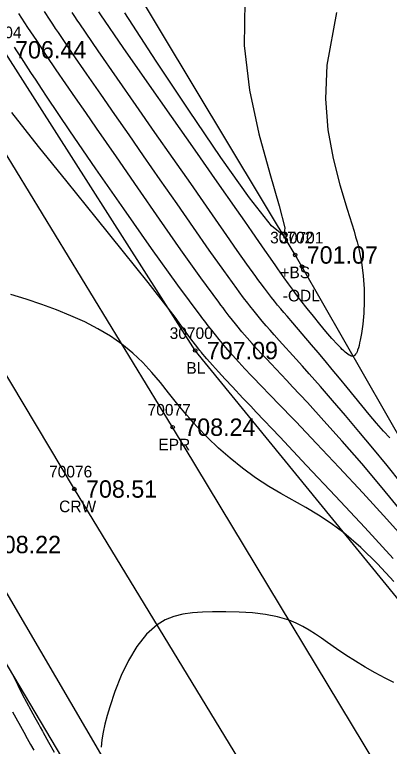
# Model space of a CAD drawing. Extents: x 1376587 to 1378239, y 1000335 to 1003031.
# Drawn here: x 1377497.4 to 1377529.7, y 1001412.8 to 1001475.9 of the extents above; entities that cross this region are included whole.
import ezdxf

# ---------------------------------------------------------------- set-up
doc = ezdxf.new("R2010")
doc.units = 0
for name, color, linetype in [('RD_DTM_BkLn1', 7, 'Continuous'), ('RD_DTM_BkLn2', 7, 'Continuous'), ('RD_DTM_BkLn_txCode', 7, 'Continuous'), ('RD_DTM_Major1', 7, 'Continuous'), ('RD_DTM_Minor1', 7, 'Continuous'), ('RD_EX_H2O', 7, 'Continuous'), ('RD_EX_H2O_txCode', 7, 'Continuous'), ('RD_EX_Road', 7, 'Continuous'), ('RD_EX_Road_txCode', 7, 'Continuous'), ('RD_EX_TX_Misc_ELEV', 7, 'Continuous'), ('RD_EX_TX_Road_ELEV', 7, 'Continuous'), ('RD_HC_Survey_ELEV', 7, 'Continuous'), ('RD_HC_Survey_txCode', 7, 'Continuous'), ('RD_SMD_Locator', 7, 'Continuous')]:
    doc.layers.add(name, color=color, linetype=linetype)

msp = doc.modelspace()

# ---------------------------------------------------------------- linework, layer by layer
at = {"layer": 'RD_DTM_BkLn1'}
for points in [[(1377890.868, 1000795.129), (1377889.749, 1000797.087), (1377860.86, 1000844.28), (1377837.196, 1000883.192), (1377805.553, 1000935.317), (1377771.668, 1000991.278), (1377739.468, 1001043.278), (1377708.639, 1001094.776), (1377678.486, 1001143.971), (1377648.112, 1001195.099), (1377620.705, 1001239.285), (1377591.743, 1001287.408), (1377561.783, 1001336.408), (1377531.285, 1001387.734), (1377502.544, 1001434.976), (1377471.981, 1001486.194), (1377441.275, 1001536.578), (1377411.042, 1001586.416), (1377380.15, 1001637.788)], [(1377581.335, 1001481.384), (1377572.966, 1001473.915), (1377568.776, 1001459.516), (1377561.131, 1001447.803), (1377550.371, 1001432.338), (1377544.546, 1001421.998), (1377539.314, 1001418.41), (1377535.53, 1001419.234), (1377512.95, 1001446.916), (1377496.428, 1001472.847), (1377478.976, 1001504.461), (1377457.669, 1001538.454), (1377441.546, 1001564.507), (1377435.353, 1001576.38), (1377438.818, 1001588.007), (1377442.54, 1001591.147), (1377470.062, 1001604.722)]]:
    msp.add_lwpolyline(points, dxfattribs=at)
at = {"layer": 'RD_DTM_BkLn2'}
msp.add_lwpolyline([(1377363.04, 1001638.463), (1377361.246, 1001636.243), (1377387.71, 1001594.226), (1377407.172, 1001565.016), (1377420.745, 1001544.524), (1377441.371, 1001508.673), (1377461.132, 1001479.016), (1377484.313, 1001440.71), (1377503.742, 1001407.975), (1377518.283, 1001383.961), (1377528.112, 1001362.148), (1377529.648, 1001353.442)], dxfattribs=at)
at = {"layer": 'RD_DTM_Major1'}
msp.add_lwpolyline([(1377530.896, 1001432.839), (1377529.068, 1001435.073), (1377527.299, 1001437.163), (1377525.617, 1001439.096), (1377524.048, 1001440.854), (1377522.617, 1001442.423), (1377521.351, 1001443.787), (1377520.84, 1001444.33), (1377520.364, 1001444.835), (1377519.917, 1001445.309), (1377519.494, 1001445.757), (1377519.09, 1001446.186), (1377518.701, 1001446.602), (1377518.272, 1001447.067), (1377517.849, 1001447.535), (1377517.423, 1001448.019), (1377516.987, 1001448.53), (1377516.534, 1001449.079), (1377516.055, 1001449.678), (1377515.886, 1001449.893), (1377515.714, 1001450.116), (1377515.537, 1001450.347), (1377515.356, 1001450.585), (1377515.169, 1001450.832), (1377514.978, 1001451.087), (1377513.45, 1001453.177), (1377511.723, 1001455.602), (1377509.879, 1001458.236), (1377507.999, 1001460.948), (1377506.162, 1001463.61), (1377504.451, 1001466.094), (1377503.525, 1001467.434), (1377502.653, 1001468.699), (1377501.813, 1001469.92), (1377500.986, 1001471.13), (1377500.154, 1001472.358), (1377499.296, 1001473.639), (1377499.051, 1001474.008), (1377498.801, 1001474.384), (1377498.547, 1001474.769), (1377498.288, 1001475.162), (1377498.024, 1001475.565), (1377497.753, 1001475.978)], dxfattribs=at)
at = {"layer": 'RD_DTM_Minor1'}
for points in [[(1377517.242, 1001477.002), (1377517.169, 1001473.227), (1377517.629, 1001469.372), (1377518.443, 1001465.599), (1377519.378, 1001462.182), (1377520.201, 1001459.394), (1377520.679, 1001457.509), (1377520.578, 1001456.8), (1377519.522, 1001457.68), (1377517.627, 1001460.086), (1377515.162, 1001463.559), (1377512.398, 1001467.641), (1377509.605, 1001471.875), (1377506.898, 1001476.041)], [(1377530.729, 1001435.454), (1377529.484, 1001437.005), (1377528.263, 1001438.503), (1377527.064, 1001439.947), (1377525.901, 1001441.325), (1377524.789, 1001442.621), (1377523.742, 1001443.824), (1377522.775, 1001444.918), (1377522.196, 1001445.566), (1377521.653, 1001446.169), (1377520.198, 1001447.778), (1377519.758, 1001448.27), (1377519.407, 1001448.665), (1377519.063, 1001449.059), (1377518.721, 1001449.459), (1377518.377, 1001449.871), (1377518.026, 1001450.303), (1377517.664, 1001450.76), (1377517.488, 1001450.987), (1377517.123, 1001451.465), (1377516.739, 1001451.979), (1377516.538, 1001452.251), (1377515.415, 1001453.804), (1377514.159, 1001455.578), (1377512.806, 1001457.514), (1377511.39, 1001459.553), (1377509.945, 1001461.639), (1377508.507, 1001463.712), (1377507.257, 1001465.506), (1377506.03, 1001467.265), (1377504.817, 1001469.007), (1377503.608, 1001470.754), (1377502.395, 1001472.525), (1377501.168, 1001474.341), (1377500.931, 1001474.695), (1377500.692, 1001475.052), (1377500.453, 1001475.413), (1377499.968, 1001476.145)], [(1377529.735, 1001439.391), (1377529.182, 1001439.97), (1377528.582, 1001440.657), (1377527.952, 1001441.411), (1377527.319, 1001442.178), (1377526.035, 1001443.742), (1377525.395, 1001444.521), (1377524.764, 1001445.284), (1377524.148, 1001446.023), (1377523.545, 1001446.737), (1377522.963, 1001447.419), (1377521.355, 1001449.292), (1377520.867, 1001449.865), (1377520.592, 1001450.192), (1377520.323, 1001450.515), (1377520.059, 1001450.836), (1377519.797, 1001451.159), (1377519.537, 1001451.487), (1377519.275, 1001451.824), (1377519.099, 1001452.054), (1377518.921, 1001452.291), (1377518.555, 1001452.785), (1377518.365, 1001453.044), (1377518.171, 1001453.313), (1377517.415, 1001454.37), (1377516.583, 1001455.551), (1377515.679, 1001456.847), (1377514.707, 1001458.248), (1377513.669, 1001459.742), (1377512.569, 1001461.32), (1377511.06, 1001463.477), (1377509.48, 1001465.729), (1377507.858, 1001468.046), (1377506.22, 1001470.398), (1377504.594, 1001472.755), (1377503.008, 1001475.087), (1377502.791, 1001475.409), (1377502.576, 1001475.73), (1377502.361, 1001476.05)], [(1377525.13, 1001476.068), (1377524.289, 1001471.517), (1377524.18, 1001468.629), (1377524.394, 1001465.952), (1377524.84, 1001463.478), (1377525.425, 1001461.199), (1377526.057, 1001459.107), (1377526.644, 1001457.195), (1377526.776, 1001456.732), (1377526.899, 1001456.278), (1377527.011, 1001455.832), (1377527.113, 1001455.394), (1377527.204, 1001454.96), (1377527.282, 1001454.531), (1377527.438, 1001453.361), (1377527.512, 1001452.225), (1377527.519, 1001451.142), (1377527.473, 1001450.129), (1377527.387, 1001449.202), (1377527.275, 1001448.378), (1377527.227, 1001448.089), (1377527.177, 1001447.819), (1377527.125, 1001447.569), (1377527.07, 1001447.341), (1377527.013, 1001447.135), (1377526.953, 1001446.952), (1377526.899, 1001446.812), (1377526.841, 1001446.692), (1377526.779, 1001446.592), (1377526.713, 1001446.515), (1377526.64, 1001446.461), (1377526.561, 1001446.431), (1377526.482, 1001446.426), (1377526.397, 1001446.441), (1377526.306, 1001446.475), (1377526.208, 1001446.527), (1377526.104, 1001446.595), (1377525.993, 1001446.679), (1377525.878, 1001446.775), (1377525.757, 1001446.884), (1377525.629, 1001447.006), (1377525.496, 1001447.139), (1377525.357, 1001447.284), (1377525.212, 1001447.438), (1377524.737, 1001447.964), (1377524.222, 1001448.557), (1377523.684, 1001449.199), (1377523.136, 1001449.871), (1377522.593, 1001450.553), (1377522.069, 1001451.226), (1377521.88, 1001451.472), (1377521.695, 1001451.715), (1377521.337, 1001452.195), (1377520.989, 1001452.67), (1377520.63, 1001453.171), (1377520.269, 1001453.685), (1377520.084, 1001453.95), (1377519.895, 1001454.223), (1377519.448, 1001454.869), (1377518.966, 1001455.568), (1377518.441, 1001456.328), (1377517.868, 1001457.157), (1377517.238, 1001458.064), (1377516.546, 1001459.059), (1377514.86, 1001461.465), (1377512.948, 1001464.185), (1377510.899, 1001467.101), (1377508.804, 1001470.097), (1377506.75, 1001473.056), (1377504.829, 1001475.861), (1377504.647, 1001476.13)], [(1377531.468, 1001430.131), (1377529.457, 1001432.388), (1377527.4, 1001434.641), (1377525.363, 1001436.831), (1377523.412, 1001438.9), (1377521.612, 1001440.786), (1377520.028, 1001442.431), (1377519.608, 1001442.865), (1377519.21, 1001443.276), (1377518.832, 1001443.668), (1377518.47, 1001444.043), (1377518.121, 1001444.405), (1377517.784, 1001444.758), (1377517.237, 1001445.337), (1377516.7, 1001445.919), (1377516.158, 1001446.524), (1377515.6, 1001447.17), (1377515.01, 1001447.878), (1377514.378, 1001448.666), (1377514.232, 1001448.851), (1377514.084, 1001449.04), (1377513.934, 1001449.235), (1377513.78, 1001449.434), (1377513.623, 1001449.639), (1377513.463, 1001449.849), (1377511.465, 1001452.542), (1377509.195, 1001455.706), (1377506.793, 1001459.126), (1377504.401, 1001462.585), (1377502.16, 1001465.87), (1377500.21, 1001468.764), (1377499.71, 1001469.513), (1377499.242, 1001470.218), (1377498.802, 1001470.886), (1377498.385, 1001471.526), (1377497.984, 1001472.145), (1377497.596, 1001472.752), (1377497.388, 1001473.08)], [(1377530.025, 1001428.991), (1377527.564, 1001431.643), (1377525.032, 1001434.359), (1377522.549, 1001437.009), (1377520.239, 1001439.466), (1377518.221, 1001441.603), (1377517.977, 1001441.861), (1377517.74, 1001442.111), (1377517.287, 1001442.589), (1377517.07, 1001442.817), (1377516.157, 1001443.781), (1377515.524, 1001444.454), (1377514.952, 1001445.072), (1377514.431, 1001445.649), (1377513.952, 1001446.2), (1377513.479, 1001446.771), (1377513.429, 1001446.833), (1377513.404, 1001446.865), (1377513.379, 1001446.896), (1377513.354, 1001446.927), (1377512.977, 1001447.415), (1377512.592, 1001447.927), (1377512.183, 1001448.482), (1377511.73, 1001449.097), (1377511.216, 1001449.787), (1377510.622, 1001450.569), (1377508.896, 1001452.778), (1377506.779, 1001455.427), (1377504.409, 1001458.368), (1377501.924, 1001461.449), (1377499.462, 1001464.521), (1377497.159, 1001467.433)], [(1377522.132, 1001454.19), (1377522.135, 1001454.192), (1377522.142, 1001454.189), (1377522.159, 1001454.174), (1377522.168, 1001454.165), (1377522.173, 1001454.155), (1377522.175, 1001454.148), (1377522.176, 1001454.143), (1377522.175, 1001454.137), (1377522.173, 1001454.133), (1377522.171, 1001454.129), (1377522.169, 1001454.127), (1377522.168, 1001454.125), (1377522.166, 1001454.125), (1377522.165, 1001454.125), (1377522.164, 1001454.127), (1377522.162, 1001454.13), (1377522.159, 1001454.134), (1377522.158, 1001454.136), (1377522.156, 1001454.139), (1377522.155, 1001454.142), (1377522.153, 1001454.144), (1377522.151, 1001454.146), (1377522.148, 1001454.154), (1377522.143, 1001454.163), (1377522.138, 1001454.172), (1377522.133, 1001454.181), (1377522.131, 1001454.187), (1377522.132, 1001454.19)], [(1377530.08, 1001427.005), (1377528.676, 1001428.511), (1377527.234, 1001429.932), (1377525.772, 1001431.196), (1377524.668, 1001432.012), (1377523.567, 1001432.729), (1377522.474, 1001433.375), (1377520.335, 1001434.576), (1377519.3, 1001435.191), (1377518.143, 1001435.952), (1377517.03, 1001436.766), (1377515.967, 1001437.623), (1377514.959, 1001438.51), (1377514.011, 1001439.416), (1377513.127, 1001440.331), (1377512.813, 1001440.673), (1377512.508, 1001441.016), (1377512.209, 1001441.361), (1377511.915, 1001441.708), (1377511.625, 1001442.059), (1377511.337, 1001442.413), (1377510.653, 1001443.273), (1377509.954, 1001444.148), (1377509.22, 1001445.021), (1377508.435, 1001445.878), (1377507.58, 1001446.702), (1377506.637, 1001447.479), (1377505.646, 1001448.163), (1377504.572, 1001448.794), (1377503.431, 1001449.377), (1377502.236, 1001449.918), (1377501.003, 1001450.421), (1377499.744, 1001450.891), (1377498.39, 1001451.354), (1377497.057, 1001451.741)], [(1377530.069, 1001418.304), (1377529.327, 1001418.661), (1377528.465, 1001419.116), (1377527.613, 1001419.606), (1377526.772, 1001420.12), (1377525.948, 1001420.651), (1377525.144, 1001421.191), (1377524.363, 1001421.73), (1377523.833, 1001422.101), (1377523.307, 1001422.46), (1377522.775, 1001422.802), (1377522.226, 1001423.12), (1377521.651, 1001423.407), (1377521.04, 1001423.656), (1377520.06, 1001423.948), (1377519.003, 1001424.156), (1377517.89, 1001424.292), (1377516.746, 1001424.368), (1377515.593, 1001424.397), (1377514.452, 1001424.39), (1377513.572, 1001424.363), (1377512.719, 1001424.301), (1377511.897, 1001424.182), (1377511.111, 1001423.985), (1377510.365, 1001423.689), (1377509.664, 1001423.273), (1377508.748, 1001422.452), (1377507.93, 1001421.405), (1377507.207, 1001420.195), (1377506.578, 1001418.882), (1377506.041, 1001417.529), (1377505.594, 1001416.197), (1377505.369, 1001415.436), (1377505.179, 1001414.706), (1377505.027, 1001414.009), (1377504.914, 1001413.345), (1377504.845, 1001412.717)], [(1377497.24, 1001418.93), (1377497.662, 1001418.073), (1377498.056, 1001417.296), (1377498.428, 1001416.584), (1377498.786, 1001415.918), (1377499.134, 1001415.282), (1377499.48, 1001414.659), (1377499.541, 1001414.548), (1377499.603, 1001414.437), (1377499.789, 1001414.103), (1377499.852, 1001413.99), (1377500.319, 1001413.149), (1377500.802, 1001412.273)], [(1377497.218, 1001415.763), (1377498.185, 1001414.012), (1377498.482, 1001413.475), (1377498.768, 1001412.957), (1377499.045, 1001412.454)]]:
    msp.add_lwpolyline(points, dxfattribs=at)
at = {"layer": 'RD_EX_H2O'}
msp.add_line((1377540.649, 1001421.744), (1377522.156, 1001454.15), dxfattribs=at)
msp.add_lwpolyline([(1377522.156, 1001454.15), (1377521.564, 1001455.155), (1377507.147, 1001479.21), (1377489.907, 1001512.216), (1377468.669, 1001546.858), (1377452.551, 1001575.953), (1377449.099, 1001585.582)], dxfattribs=at)
at = {"layer": 'RD_EX_Road'}
for points in [[(1377899.668, 1000800.294), (1377898.717, 1000801.843), (1377870.308, 1000849.935), (1377847.281, 1000887.888), (1377815.153, 1000940.575), (1377781.512, 1000995.259), (1377748.623, 1001049.208), (1377716.579, 1001099.532), (1377686.671, 1001148.78), (1377656.469, 1001199.107), (1377629.542, 1001244.184), (1377599.886, 1001292.672), (1377570.873, 1001341.428), (1377539.828, 1001392.468), (1377511.01, 1001440.306), (1377480.717, 1001489.998), (1377449.725, 1001541.494), (1377420.899, 1001591.946), (1377390.45, 1001644.414)], [(1377883.752, 1000788.501), (1377882.63, 1000790.224), (1377852.259, 1000839.599), (1377828.464, 1000879.313), (1377796.997, 1000930.663), (1377763.067, 1000986.649), (1377731.866, 1001037.813), (1377700.311, 1001089.979), (1377670.429, 1001138.24), (1377639.732, 1001190.031), (1377611.891, 1001234.227), (1377582.777, 1001282.571), (1377552.217, 1001331.03), (1377522.243, 1001382.346), (1377494.257, 1001430.189), (1377463.172, 1001481.135), (1377433.415, 1001531.286), (1377403.141, 1001580.977), (1377371.36, 1001632.192)]]:
    msp.add_lwpolyline(points, dxfattribs=at)
at = {"layer": 'RD_SMD_Locator'}
for centre in [(1377521.564, 1001455.155), (1377522.156, 1001454.15), (1377512.95, 1001446.916), (1377511.01, 1001440.306), (1377502.544, 1001434.976)]:
    msp.add_circle(centre, 0.15, dxfattribs=at)

# ---------------------------------------------------------------- texts
at = {"layer": 'RD_DTM_BkLn_txCode'}
for s, p in [('30704', (1377494.271, 1001473.847)), ('30702', (1377519.407, 1001456.155)), ('+BS', (1377520.296, 1001453.155)), ('30700', (1377510.753, 1001447.916)), ('BL', (1377512.194, 1001444.916))]:
    msp.add_text(s, height=1, dxfattribs=at).set_placement(p)
at = {"layer": 'RD_EX_H2O_txCode'}
for s, p in [('30701', (1377520.282, 1001456.15)), ('-ODL', (1377520.502, 1001451.15))]:
    msp.add_text(s, height=1, dxfattribs=at).set_placement(p)
at = {"layer": 'RD_EX_Road_txCode'}
for s, p in [('70077', (1377508.853, 1001441.306)), ('EPR', (1377509.782, 1001438.306))]:
    msp.add_text(s, height=1, dxfattribs=at).set_placement(p)
at = {"layer": 'RD_EX_TX_Misc_ELEV'}
for s, p in [('706.44', (1377497.428, 1001472.097)), ('701.07', (1377522.564, 1001454.405)), ('707.09', (1377513.95, 1001446.166))]:
    msp.add_text(s, height=1.5, dxfattribs=at).set_placement(p)
at = {"layer": 'RD_EX_TX_Road_ELEV'}
for s, p in [('708.24', (1377512.01, 1001439.556)), ('708.22', (1377495.257, 1001429.439))]:
    msp.add_text(s, height=1.5, dxfattribs=at).set_placement(p)
at = {"layer": 'RD_HC_Survey_ELEV'}
msp.add_text('708.51', height=1.5, dxfattribs=at).set_placement((1377503.544, 1001434.226))
at = {"layer": 'RD_HC_Survey_txCode'}
for s, p in [('70076', (1377500.363, 1001435.976)), ('CRW', (1377501.229, 1001432.976))]:
    msp.add_text(s, height=1, dxfattribs=at).set_placement(p)

doc.saveas('drawing.dxf')
